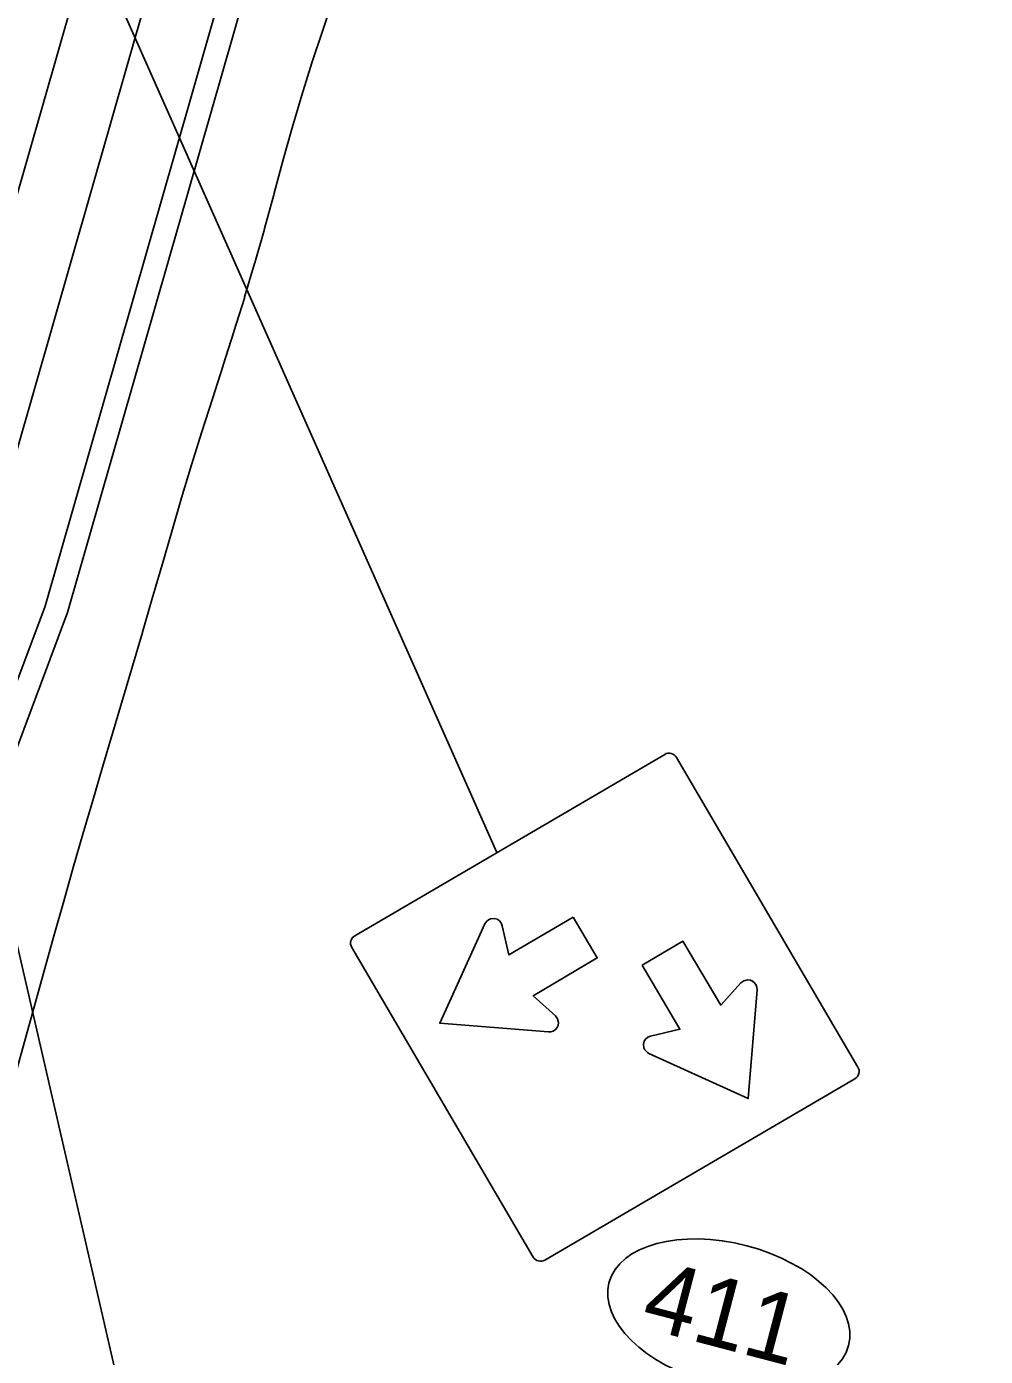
# Model space of a CAD drawing. Extents: x 2096670 to 2098561, y 684033 to 689893.
# Drawn here: x 2097948.6 to 2098112.5, y 689091.3 to 689318.8 of the extents above; entities that cross this region are included whole.
import ezdxf

# ---------------------------------------------------------------- set-up
doc = ezdxf.new("R2010")
doc.units = 0
for name, color, linetype in [('Exist CMT EOP', 7, 'Continuous'), ('Prop Sign E', 7, 'Continuous'), ('Prop Sign E One Way_Right CELL', 7, 'Continuous'), ('Scratch_Level_4', 7, 'Continuous')]:
    doc.layers.add(name, color=color, linetype=linetype)

msp = doc.modelspace()

# ---------------------------------------------------------------- linework, layer by layer
at = {"layer": 'Exist CMT EOP'}
for p, q in [((2097898.92, 689078.74), (2098112.47, 689824.77)), ((2097951.73, 689219.64), (2098006.77, 689411.92)), ((2097955.58, 689218.54), (2098010.62, 689410.82)), ((2097859.86, 688985.9), (2097968.29, 689364.69)), ((2097898.92, 689078.74), (2097951.73, 689219.64)), ((2097902.76, 689077.64), (2097955.58, 689218.54))]:
    msp.add_line(p, q, dxfattribs=at)
at = {"layer": 'Prop Sign E'}
for p, q in [((2098004.67, 689163.24), (2098057.66, 689194.26)), ((2098090.68, 689140.76), (2098059.65, 689193.74)), ((2098035.17, 689108.26), (2098004.15, 689161.24)), ((2098037.17, 689107.74), (2098090.15, 689138.76))]:
    msp.add_line(p, q, dxfattribs=at)
for points in [[(2098042, 689166.41), (2098031.03, 689159.94), (2098029.88, 689164.95), (2098029.7, 689165.41), (2098029.35, 689165.84), (2098028.99, 689166.04), (2098028.49, 689166.18), (2098027.87, 689166.11), (2098027.53, 689165.94), (2098027.27, 689165.74), (2098027.08, 689165.5), (2098026.92, 689165.26), (2098019.19, 689148.25), (2098037.8, 689146.76), (2098038.19, 689146.78), (2098038.58, 689146.92), (2098038.99, 689147.18), (2098039.27, 689147.53), (2098039.42, 689147.85), (2098039.5, 689148.37), (2098039.35, 689149.01), (2098038.98, 689149.51), (2098035.17, 689152.97), (2098046.11, 689159.44)], [(2098053.78, 689158.19), (2098060.25, 689147.22), (2098055.24, 689146.06), (2098054.78, 689145.88), (2098054.35, 689145.53), (2098054.15, 689145.18), (2098054.01, 689144.67), (2098054.08, 689144.06), (2098054.26, 689143.72), (2098054.46, 689143.46), (2098054.69, 689143.26), (2098054.93, 689143.1), (2098071.94, 689135.37), (2098073.43, 689153.99), (2098073.42, 689154.38), (2098073.28, 689154.76), (2098073.02, 689155.17), (2098072.66, 689155.45), (2098072.34, 689155.61), (2098071.83, 689155.68), (2098071.19, 689155.54), (2098070.69, 689155.16), (2098067.22, 689151.36), (2098060.76, 689162.29)]]:
    msp.add_lwpolyline(points, close=True, dxfattribs=at)
for centre, start, end in [((2098058.39, 689193), 30.3503, 120.3503), ((2098005.41, 689161.98), 120.3503, 210.3503), ((2098089.42, 689140.02), 300.3503, 30.3503), ((2098036.43, 689109), 210.3503, 300.3503)]:
    msp.add_arc(centre, 1.46, start, end, dxfattribs=at)
msp.add_ellipse((2098068.61, 689098.48), major_axis=(-20.49, 5.37), ratio=0.571429, dxfattribs=at)
at = {"layer": 'Prop Sign E One Way_Right CELL'}
for p, q in [((2098028.97, 689177.47), (2097961.62, 689329.16)), ((2097983.65, 689002.74), (2097920.17, 689277.15))]:
    msp.add_line(p, q, dxfattribs=at)
at = {"layer": 'Scratch_Level_4'}
for p, q in [((2097990.81, 689290.01), (2097989.23, 689284.23)), ((2097989.21, 689284.14), (2097987.58, 689278.36)), ((2097987.54, 689278.24), (2097985.84, 689272.49)), ((2097985.8, 689272.33), (2097984.01, 689266.6)), ((2097983.99, 689266.53), (2097982.17, 689260.82)), ((2097970.05, 689220.9), (2097968.37, 689215.14)), ((2097968.36, 689215.1), (2097966.67, 689209.34)), ((2097966.66, 689209.33), (2097964.96, 689203.58))]:
    msp.add_line(p, q, dxfattribs=at)
for points in [[(2098001.11, 689323.85), (2097999.21, 689318.18), (2097997.35, 689312.58), (2097995.6, 689307.03), (2097993.96, 689301.46), (2097992.39, 689295.79), (2097990.82, 689290.03)], [(2097982.16, 689260.78), (2097980.33, 689255.09), (2097978.52, 689249.42), (2097976.76, 689243.78), (2097975.06, 689238.12), (2097973.38, 689232.41), (2097971.72, 689226.67), (2097970.05, 689220.91)], [(2097964.96, 689203.57), (2097963.25, 689197.82), (2097961.55, 689192.08), (2097959.86, 689186.35), (2097958.19, 689180.62), (2097956.54, 689174.88), (2097954.9, 689169.14), (2097953.27, 689163.39), (2097951.66, 689157.64), (2097950.06, 689151.88), (2097948.47, 689146.12), (2097946.89, 689140.34), (2097945.31, 689134.56)]]:
    msp.add_lwpolyline(points, dxfattribs=at)
for centre, start, end in [((2097980.2, 689292.92), 344.6945, 344.7718), ((2097978.62, 689287.13), 344.2248, 344.6945), ((2097976.99, 689281.36), 343.5755, 344.2248), ((2097975.29, 689275.6), 342.7057, 343.5755), ((2097973.51, 689269.87), 342.3259, 342.7057), ((2097971.69, 689264.16), 342.1569, 342.3259), ((2097959.49, 689223.97), 343.7885, 343.8683), ((2097957.81, 689218.21), 343.5873, 343.7885), ((2097956.12, 689212.45), 343.4943, 343.5873), ((2097954.41, 689206.7), 343.4586, 343.4943)]:
    msp.add_arc(centre, 11, start, end, dxfattribs=at)

# ---------------------------------------------------------------- texts
at = {"layer": 'Prop Sign E'}
msp.add_text('411', height=11.958, rotation=345.3163, dxfattribs=at).set_placement((2098053.25, 689096.33))

doc.saveas('drawing.dxf')
